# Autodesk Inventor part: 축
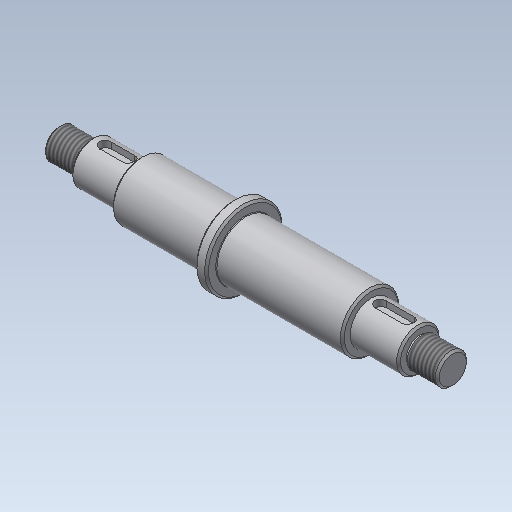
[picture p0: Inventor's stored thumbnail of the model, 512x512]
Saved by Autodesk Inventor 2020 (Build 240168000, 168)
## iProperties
CustomPartVersion: 1
Created: 2021-06
Part Number: 축
Material: 강철, 연강
Document SubType Name: Modeling
Designer: mdu
Density: 1 g/cm^3
Appearance: 흰색
Author: mdu
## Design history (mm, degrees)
sketch "주 스케치"
  geometry: L1 (0, 0)-(203, 0) reference; L2 (0, 0)-(0, 8); L3 (0, 8)-(17, 8); L4 (17, 8)-(17, 11); L5 (17, 11)-(42, 11); L6 (42, 11)-(42, 15); L7 (42, 15)-(90, 15); L8 (90, 15)-(90, 20); L9 (96, 20)-(96, 15); L10 (90, 20)-(96, 20); L11 (161, 15)-(161, 11); L12 (96, 15)-(161, 15); L13 (186, 11)-(186, 8); L14 (161, 11)-(186, 11); L15 (203, 8)-(203, 0); L16 (186, 8)-(203, 8)
  constraints: 32 end point, 9 horizontal, 8 vertical
  dimensions: "d3" = 16 diameter of L3 L1 (derived); "d4" = 22 diameter of L5 L1 (derived); "d5" = 30 diameter of L7 L1 (derived); "d6" = 40 diameter of L10 L1 (derived); "d7" = 30 diameter of L12 L1 (derived); "d8" = 22 diameter of L14 L1 (derived); "d9" = 16 diameter of L16 L1 (derived)
revolve "회전1" sketch "주 스케치" stored, may be unused: angle "d10" = 0 deg
chamfer "모따기1" distance "d11" = 1; stored, may be unused: second distance "d12" = 1, angle "d13" = 45 deg
chamfer "모따기2" distance "d14" = 1; stored, may be unused: second distance "d15" = 1, angle "d16" = 45 deg
node "키홈1"
chamfer "모따기3" distance "d17" = 1; stored, may be unused: second distance "d18" = 1, angle "d19" = 45 deg
fillet "모깎기1" dims "d20" = 0.3
chamfer "모따기4" distance "d21" = 1; stored, may be unused: second distance "d22" = 1, angle "d23" = 45 deg
chamfer "모따기5" distance "d24" = 1; stored, may be unused: second distance "d25" = 1, angle "d26" = 45 deg
fillet "모깎기2" dims "d27" = 0.3
chamfer "모따기6" distance "d28" = 1; stored, may be unused: second distance "d29" = 1, angle "d30" = 45 deg
chamfer "모따기7" distance "d31" = 1; stored, may be unused: second distance "d32" = 1, angle "d33" = 45 deg
node "키홈2"
chamfer "모따기8" distance "d34" = 1; stored, may be unused: second distance "d35" = 1, angle "d36" = 45 deg
sketch "스케치3"
  geometry: L1 (1, 8)-(17, 8) reference; L2 (17, -10)-(17, 10) reference; L3 (186, 10)-(186, -10) reference; L4 (186, 8)-(202, 8) reference; L5 (203, 7)-(203, -7) reference; L6 (0, 0)-(203, 0); L7 (17, 8)-(15.5, 8); L8 (15.5, 8)-(15.5, 7); L9 (15.5, 7)-(17, 7); L10 (17, 7)-(17, 8); L11 (186, 8)-(187.5, 8); L12 (187.5, 8)-(187.5, 7); L13 (187.5, 7)-(186, 7); L14 (186, 7)-(186, 8)
  constraints: 18 end point, 4 parallel, 2 horizontal, 2 perpendicular, 1 midpoint
  dimensions: "d37" = 14 diameter of L13 L6; "d39" = 1.5 distance of L12.end L13.end; "d40" = 14 diameter of L9 L6; "d41" = 1.5 distance of L8.end L9.end
revolve "회전2" sketch "스케치3" stored, may be unused: angle "d42" = 90 deg
feature "스레드1" dims "d43" = 10, "d44" = 0
feature "스레드2" dims "d45" = 10, "d46" = 0
sketch "스케치4"
  geometry: L1 (186, 7)-(186, -7) reference; L2 (186, 10)-(186, -10) reference; L3 (161, -11)-(185, -11) reference; L4 (165.225, -11)-(165.225, -9); L5 (165.225, -9)-(167.225, -11); L6 (165.225, -11)-(167.225, -11); 1 further point
  constraints: 6 end point, 2 point on line, 1 collinear, 1 perpendicular
  dimensions: "d47" = 20.77468 distance from line of L2 L4.start; "d48" = 4 diameter of L5.end L4; "d49" = 45 deg angle of L4 L5
revolve "회전3" sketch "스케치4" stored, may be unused: angle "d50" = 90 deg
node "솔리드1"
feature "iFeature3:1"
feature "iFeature3:2"
node "투영된 루프1"
other parameters: "d0" = 0, "d1" = 0, "d2" = 0
